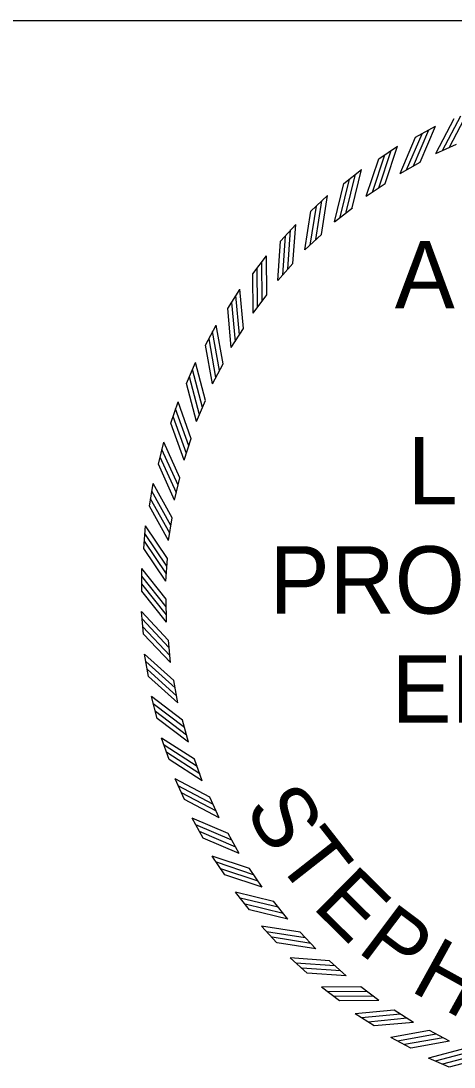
# Model space of a CAD drawing. Extents: x 16 to 1228740, y 11 to 152440.
# Drawn here: x 17.6651 to 17.737, y 10.8249 to 10.9986 of the extents above; entities that cross this region are included whole.
import ezdxf

# ---------------------------------------------------------------- set-up
doc = ezdxf.new("R2010")
doc.units = 0
doc.layers.add('R_No Plot', color=7, linetype='Continuous')
doc.layers.add('STAMP_FRED', color=7, linetype='Continuous')

msp = doc.modelspace()

# ---------------------------------------------------------------- linework, layer by layer
at = {"layer": 'R_No Plot'}
msp.add_line((17.888, 10.99864), (17.47349, 10.99864), dxfattribs=at)
at = {"layer": 'STAMP_FRED'}
for p, q in [((17.73063, 10.97933), (17.73393, 10.98116)), ((17.72451, 10.97573), (17.72764, 10.97782)), ((17.73398, 10.97665), (17.73743, 10.9782)), ((17.7187, 10.97163), (17.72166, 10.97397)), ((17.72807, 10.97333), (17.73138, 10.97516)), ((17.72245, 10.96953), (17.7256, 10.97163)), ((17.71326, 10.96706), (17.71601, 10.96964)), ((17.71717, 10.96529), (17.72013, 10.96763)), ((17.70821, 10.96206), (17.71073, 10.96486)), ((17.71225, 10.96062), (17.71501, 10.9632)), ((17.70359, 10.95666), (17.70587, 10.95966)), ((17.70773, 10.95555), (17.71027, 10.95836)), ((17.69943, 10.9509), (17.70146, 10.95407)), ((17.70365, 10.95014), (17.70595, 10.95314)), ((17.69576, 10.94481), (17.69752, 10.94815)), ((17.70003, 10.9444), (17.70207, 10.94759)), ((17.69261, 10.93845), (17.69409, 10.94191)), ((17.6969, 10.93839), (17.69867, 10.94173)), ((17.69427, 10.93214), (17.69576, 10.93561)), ((17.68999, 10.93184), (17.69118, 10.93542)), ((17.68793, 10.92504), (17.68882, 10.9287)), ((17.69217, 10.92569), (17.69336, 10.92928)), ((17.68643, 10.91809), (17.68702, 10.92182)), ((17.69061, 10.91909), (17.6915, 10.92276)), ((17.68552, 10.91104), (17.68579, 10.9148)), ((17.6896, 10.91239), (17.69018, 10.91612)), ((17.68519, 10.90395), (17.68515, 10.90772)), ((17.68914, 10.90562), (17.68942, 10.90939)), ((17.68925, 10.89884), (17.68921, 10.90262)), ((17.68545, 10.89684), (17.6851, 10.9006)), ((17.68991, 10.89209), (17.68957, 10.89585)), ((17.68629, 10.88979), (17.68563, 10.8935)), ((17.69113, 10.88542), (17.69048, 10.88914)), ((17.68771, 10.88283), (17.68675, 10.88647)), ((17.6929, 10.87887), (17.69194, 10.88253)), ((17.6897, 10.876), (17.68845, 10.87956)), ((17.6952, 10.87249), (17.69394, 10.87605)), ((17.69225, 10.86937), (17.69071, 10.87281)), ((17.69802, 10.86632), (17.69647, 10.86977)), ((17.69534, 10.86297), (17.69352, 10.86627)), ((17.70134, 10.86041), (17.69951, 10.86372)), ((17.69895, 10.85685), (17.69686, 10.85999)), ((17.70514, 10.85479), (17.70304, 10.85794)), ((17.70305, 10.85104), (17.7007, 10.854)), ((17.70939, 10.84951), (17.70704, 10.85247)), ((17.70761, 10.8456), (17.70503, 10.84835)), ((17.71406, 10.84459), (17.71147, 10.84735)), ((17.71261, 10.84055), (17.70981, 10.84308)), ((17.71912, 10.84007), (17.71631, 10.84261)), ((17.71801, 10.83593), (17.71501, 10.83822)), ((17.72453, 10.83599), (17.72153, 10.83829)), ((17.72377, 10.83177), (17.7206, 10.8338)), ((17.73027, 10.83237), (17.72709, 10.83441)), ((17.72986, 10.8281), (17.72653, 10.82986)), ((17.73628, 10.82924), (17.73294, 10.83101)), ((17.73623, 10.82495), (17.73276, 10.82643))]:
    msp.add_line(p, q, dxfattribs=at)
for points in [[(17.73398, 10.97665), (17.73703, 10.98241)], [(17.73509, 10.97713), (17.73814, 10.9829)], [(17.73628, 10.9777), (17.73932, 10.98347)], [(17.73137, 10.97516), (17.73393, 10.98116)], [(17.72807, 10.97333), (17.73063, 10.97933)], [(17.72914, 10.9739), (17.7317, 10.9799)], [(17.73027, 10.97456), (17.73283, 10.98056)], [(17.72559, 10.97163), (17.72765, 10.97782)], [(17.72245, 10.96953), (17.72451, 10.97572)], [(17.72347, 10.97019), (17.72552, 10.97638)], [(17.72454, 10.97094), (17.72659, 10.97713)], [(17.72012, 10.96763), (17.72166, 10.97397)], [(17.71812, 10.96603), (17.71966, 10.97236)], [(17.71913, 10.96686), (17.72067, 10.9732)], [(17.71716, 10.96528), (17.7187, 10.97162)], [(17.71408, 10.96235), (17.71508, 10.96879)], [(17.715, 10.9632), (17.71601, 10.96964)], [(17.71225, 10.96061), (17.71326, 10.96705)], [(17.71314, 10.96143), (17.71415, 10.96788)], [(17.70941, 10.95743), (17.70988, 10.96394)], [(17.71026, 10.95836), (17.71073, 10.96486)], [(17.70773, 10.95555), (17.70821, 10.96205)], [(17.70856, 10.95644), (17.70903, 10.96295)], [(17.70517, 10.95215), (17.7051, 10.95867)], [(17.70594, 10.95314), (17.70587, 10.95966)], [(17.70365, 10.95013), (17.70359, 10.95666)], [(17.7044, 10.95109), (17.70433, 10.95761)], [(17.70138, 10.94653), (17.70077, 10.95303)], [(17.70207, 10.94758), (17.70146, 10.95408)], [(17.7007, 10.94541), (17.70009, 10.95191)], [(17.70003, 10.9444), (17.69943, 10.95089)], [(17.69866, 10.94173), (17.69752, 10.94815)], [(17.69806, 10.94062), (17.69692, 10.94705)], [(17.6969, 10.93838), (17.69576, 10.94481)], [(17.69748, 10.93945), (17.69634, 10.94587)], [(17.69525, 10.93446), (17.69358, 10.94077)], [(17.69575, 10.93561), (17.69409, 10.94192)], [(17.69476, 10.93324), (17.69309, 10.93955)], [(17.69427, 10.93213), (17.69261, 10.93844)], [(17.69295, 10.92808), (17.69077, 10.93423)], [(17.69336, 10.92927), (17.69118, 10.93542)], [(17.69257, 10.92683), (17.69038, 10.93298)], [(17.69217, 10.92569), (17.68999, 10.93183)], [(17.6915, 10.92276), (17.68882, 10.92871)], [(17.69119, 10.92154), (17.68851, 10.92749)], [(17.69091, 10.92026), (17.68823, 10.92621)], [(17.69061, 10.91909), (17.68793, 10.92503)], [(17.69018, 10.91611), (17.68702, 10.92182)], [(17.68997, 10.91488), (17.68681, 10.92058)], [(17.6898, 10.91358), (17.68663, 10.91928)], [(17.6896, 10.91238), (17.68644, 10.91809)], [(17.68942, 10.90938), (17.68579, 10.91481)], [(17.68931, 10.90813), (17.68569, 10.91356)], [(17.68924, 10.90682), (17.68562, 10.91225)], [(17.68914, 10.90561), (17.68552, 10.91104)], [(17.68921, 10.90261), (17.68515, 10.90772)], [(17.68921, 10.90136), (17.68515, 10.90646)], [(17.68925, 10.90005), (17.68519, 10.90515)], [(17.68925, 10.89883), (17.68519, 10.90394)], [(17.68956, 10.89585), (17.6851, 10.9006)], [(17.68967, 10.8946), (17.6852, 10.89935)], [(17.68982, 10.89329), (17.68535, 10.89805)], [(17.68992, 10.89209), (17.68545, 10.89684)], [(17.69047, 10.88913), (17.68563, 10.8935)], [(17.69068, 10.8879), (17.68584, 10.89226)], [(17.69094, 10.88661), (17.68609, 10.89098)], [(17.69114, 10.88541), (17.68629, 10.88978)], [(17.69194, 10.88252), (17.68675, 10.88647)], [(17.69224, 10.8813), (17.68706, 10.88526)], [(17.69261, 10.88004), (17.68742, 10.884)], [(17.6929, 10.87887), (17.68772, 10.88282)], [(17.69394, 10.87605), (17.68844, 10.87956)], [(17.69435, 10.87486), (17.68885, 10.87837)], [(17.69481, 10.87364), (17.68931, 10.87715)], [(17.69521, 10.87249), (17.68971, 10.876)], [(17.69647, 10.86977), (17.6907, 10.87281)], [(17.69698, 10.86862), (17.69121, 10.87166)], [(17.69754, 10.86743), (17.69177, 10.87048)], [(17.69803, 10.86632), (17.69226, 10.86937)], [(17.69951, 10.86371), (17.69351, 10.86627)], [(17.70011, 10.86261), (17.69411, 10.86517)], [(17.70077, 10.86148), (17.69477, 10.86404)], [(17.70135, 10.86041), (17.69535, 10.86297)], [(17.70304, 10.85793), (17.69685, 10.85999)], [(17.70373, 10.85688), (17.69754, 10.85894)], [(17.70448, 10.85581), (17.69829, 10.85786)], [(17.70514, 10.85479), (17.69895, 10.85685)], [(17.70704, 10.85246), (17.7007, 10.854)], [(17.70781, 10.85147), (17.70147, 10.85301)], [(17.70865, 10.85046), (17.70231, 10.852)], [(17.70939, 10.84951), (17.70305, 10.85104)], [(17.71147, 10.84734), (17.70503, 10.84835)], [(17.71232, 10.84642), (17.70588, 10.84742)], [(17.71324, 10.84548), (17.7068, 10.84649)], [(17.71406, 10.84459), (17.70762, 10.8456)], [(17.71632, 10.8426), (17.70981, 10.84308)], [(17.71724, 10.84175), (17.71073, 10.84222)], [(17.71823, 10.8409), (17.71173, 10.84137)], [(17.71912, 10.84007), (17.71262, 10.84055)], [(17.72153, 10.83828), (17.71501, 10.83822)], [(17.72252, 10.83751), (17.716, 10.83744)], [(17.72358, 10.83674), (17.71706, 10.83667)], [(17.72454, 10.83599), (17.71802, 10.83593)], [(17.72709, 10.83441), (17.72059, 10.8338)], [(17.72814, 10.83372), (17.72165, 10.83311)], [(17.72926, 10.83304), (17.72276, 10.83243)], [(17.73027, 10.83237), (17.72378, 10.83177)], [(17.73295, 10.831), (17.72652, 10.82986)], [(17.73405, 10.8304), (17.72763, 10.82926)], [(17.73522, 10.82982), (17.7288, 10.82868)], [(17.73629, 10.82924), (17.72987, 10.8281)], [(17.73906, 10.82809), (17.73276, 10.82643)], [(17.74021, 10.82759), (17.73391, 10.82592)], [(17.74143, 10.8271), (17.73512, 10.82543)], [(17.74254, 10.82661), (17.73623, 10.82495)]]:
    msp.add_lwpolyline(points, dxfattribs=at)

# ---------------------------------------------------------------- texts
for s, height, p in [('ARKANSAS', 0.011193, (17.72717, 10.95089)), ('LICENSED', 0.011193, (17.7293, 10.91835)), ('PROFESSIONAL', 0.0111934, (17.70638, 10.90023)), ('ENGINEER', 0.011193, (17.72663, 10.88211))]:
    msp.add_text(s, height=height, dxfattribs=at).set_placement(p)
for s, rotation, p in [('S', 300.7985, (17.70208, 10.86787)), ('T', 308.0945, (17.70716, 10.85934)), ('E', 315.3905, (17.71329, 10.85152)), ('P', 323.0513, (17.72074, 10.84422)), ('H', 331.0769, (17.72951, 10.83771))]:
    msp.add_text(s, height=0.01042, rotation=rotation, dxfattribs=at).set_placement(p)

doc.saveas('drawing.dxf')
